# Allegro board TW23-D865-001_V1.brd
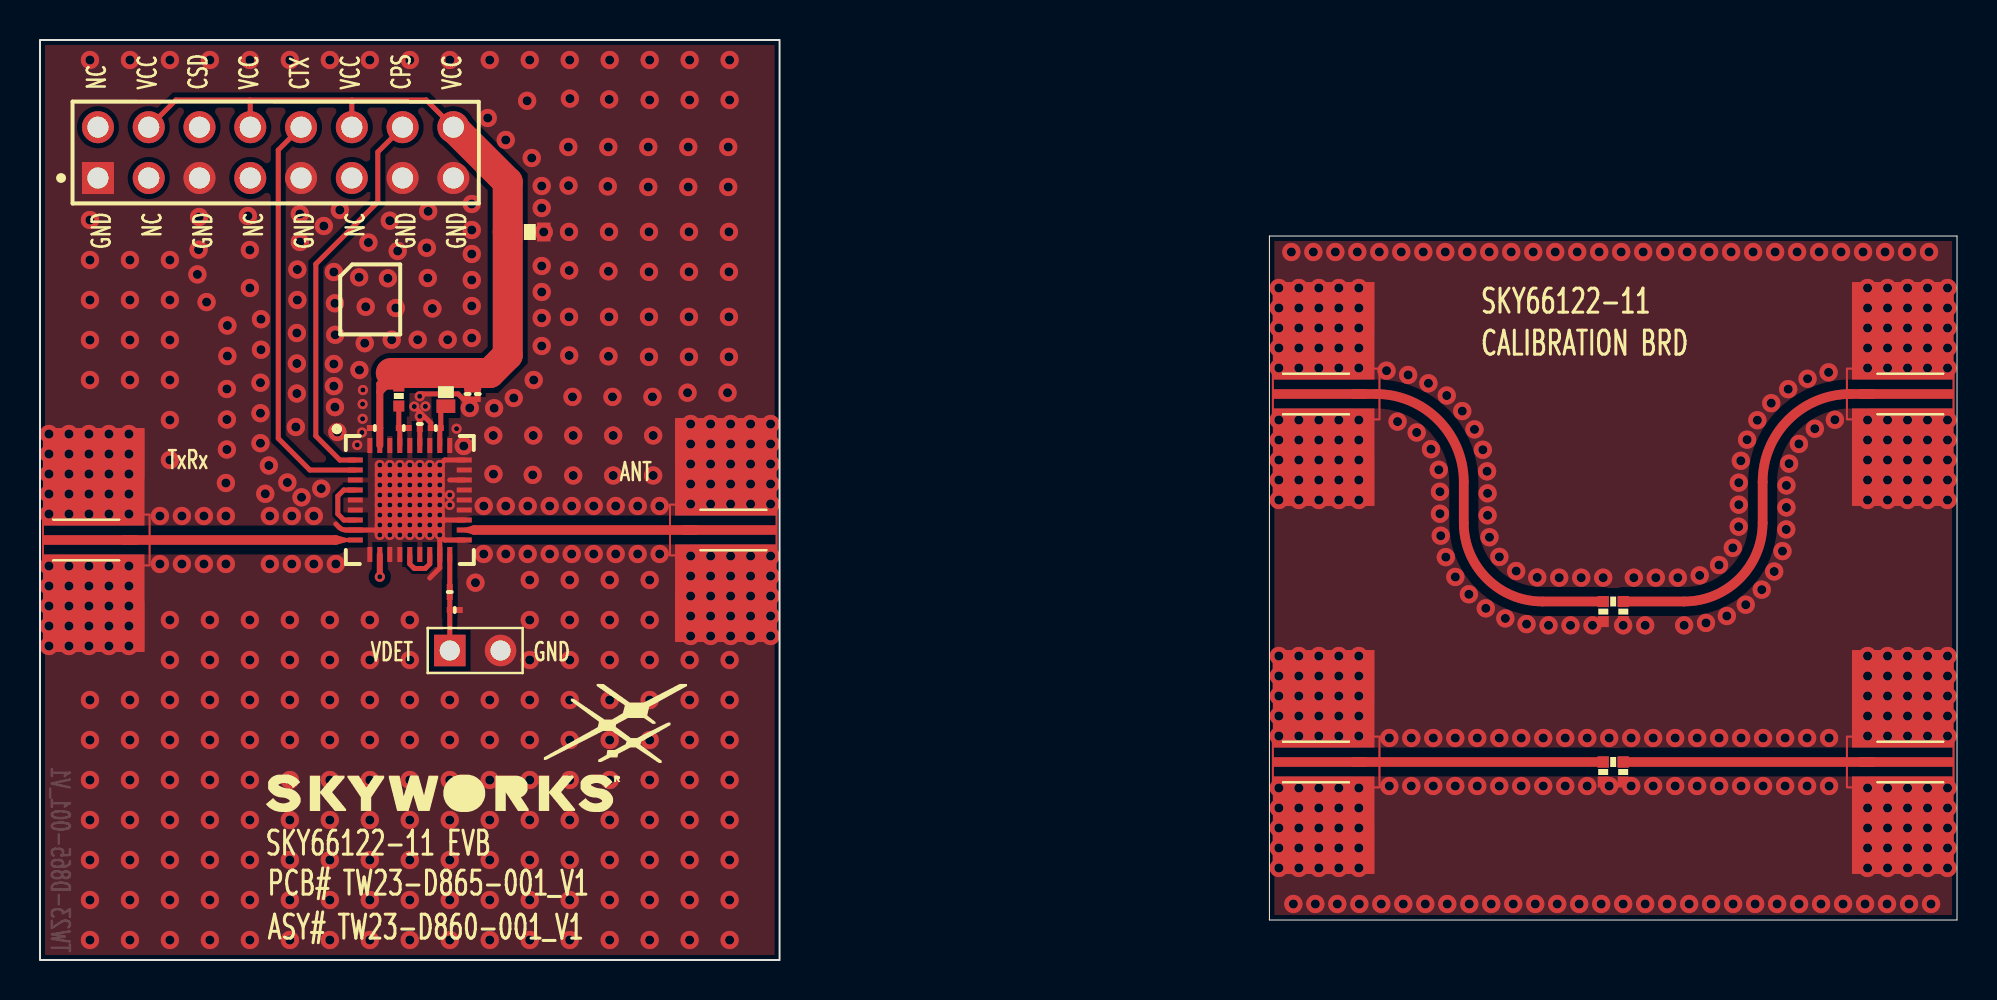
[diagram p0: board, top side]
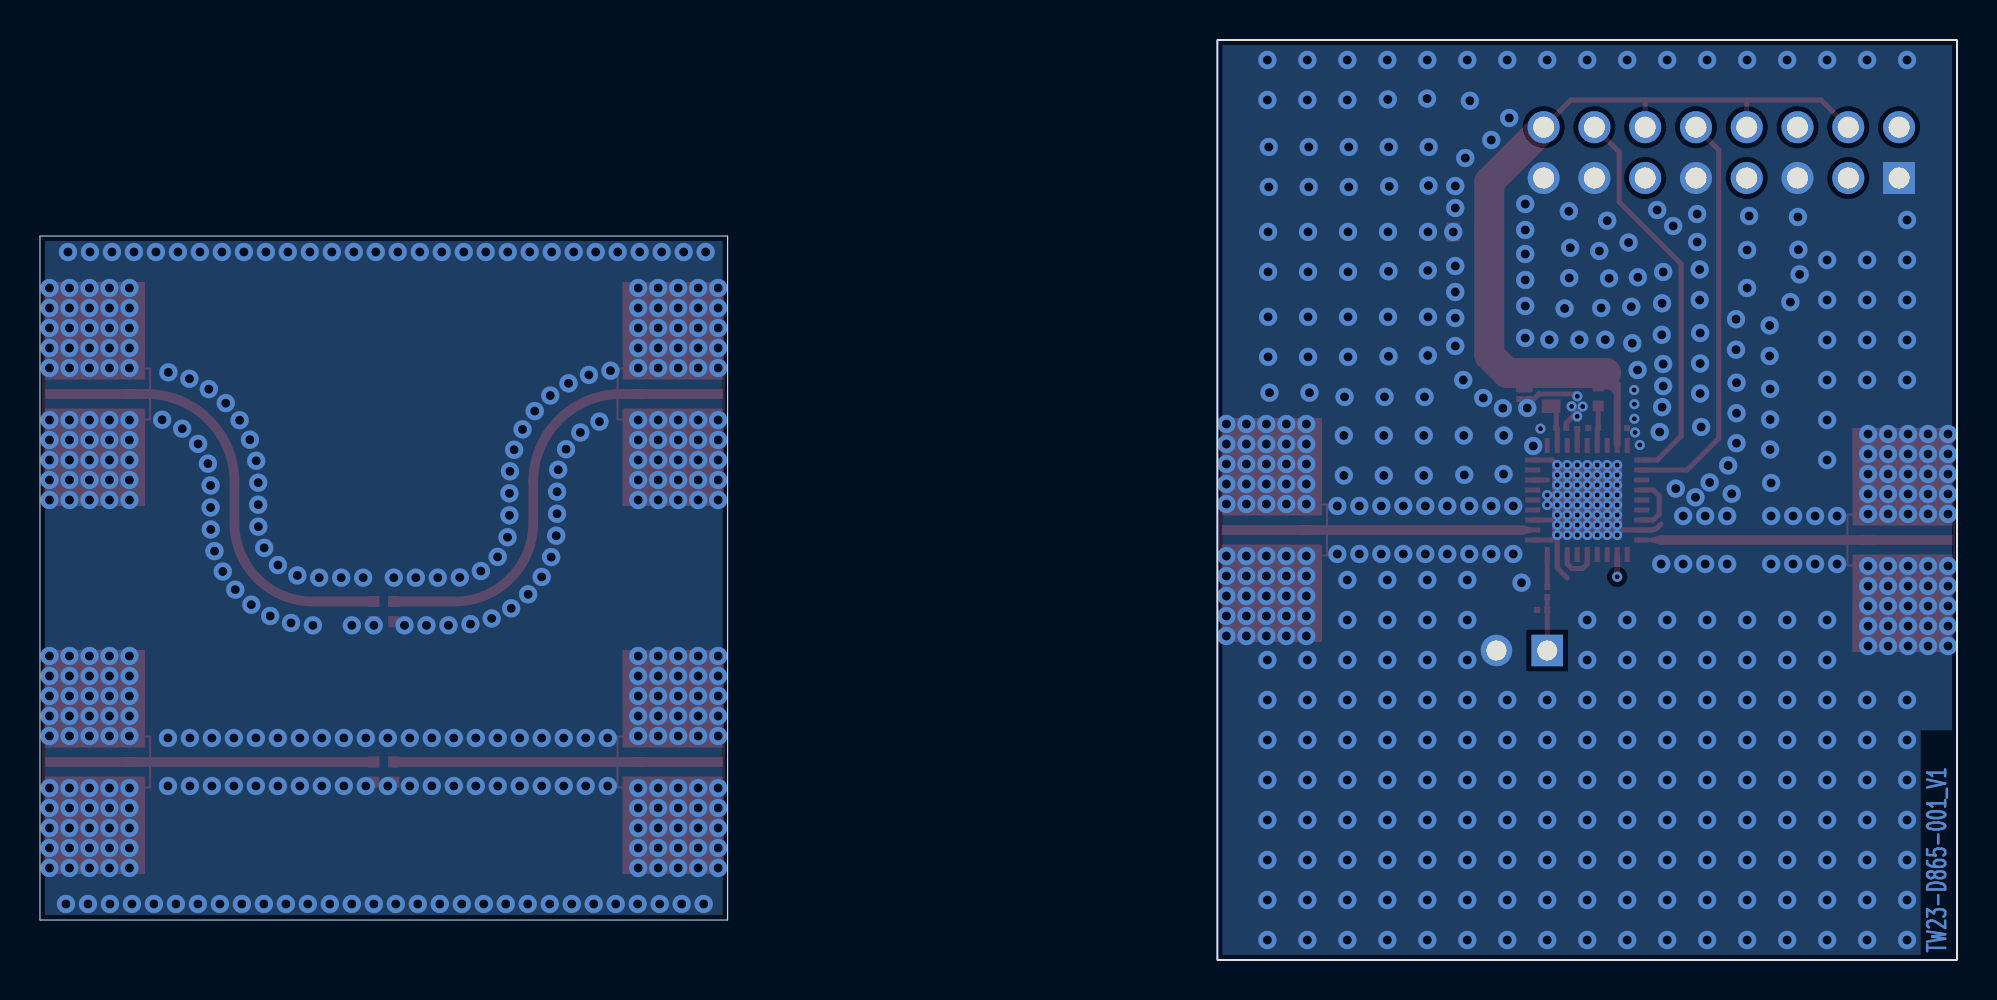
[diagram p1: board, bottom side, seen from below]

Outline 95.9 x 46 mm; copper layers: TOP, L2, L3, BOTTOM. Coordinates in mm from the lower left corner of the outline.
Outline path: rectangle 0,0 37,46 ; 61.5,36.2 61.5,2 95.9,2 95.9,36.2 61.5,36.2

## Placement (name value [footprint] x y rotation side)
ANT  SMA  [SSMA]  95.72 9.9 0 top
C1  -  [0201]  19.8 26.6 0 top
C3  -  [0201]  16.75 26.6 0 top
C5  -  [0201]  18.2 26.6 180 top
C6  -  [0201]  21.39 28.3 270 top
C7  -  [0201]  21.9 28.3 270 top
C8  -  [0201]  19 26.8 270 top
C9  -  [0603]  24.5 36.4 0 top
C10  -  [0201]  20.75 17.5 0 top
J1  ANT  [SSMA]  36.85 21.5 0 top
J2  Header_7  [HDR2540P1RST-2]  21.77 15.47 0 top
J3  TX_RX  [SSMA]  0.15 21 180 top
J5  CON16A  [HDRV2X8_2540P]  2.9 39.1 0 top
J44  SMA  [SSMA]  95.72 28.3 0 top
JM44  SMA  [SSMA]  61.68 28.3 180 top
L3  -  [0402]  17.95 28.2 90 top
L4  -  [0603]  20.3 28.39 90 top
NOREF  -  []  -46.4 -55.15 0 top
NOREF#2  -  []  95.9 2 90 top
NOREF#3  -  []  61.5 36.2 0 top
NOREF#4  -  []  120.8 27.75 0 top
NOREF#5  -  []  11.3 7.4 0 top
NOREF#6  -  []  0 0 90 top
NOREF#7  -  []  0 46 0 top
NOREF#8  -  []  -46.45 -113.82 0 top
NOREF#9  -  []  118.6 -25.15 0 top
NOREF#10  -  []  151.3 -8.35 0 top
R1  -  [0201]  20.5 18.4 270 top
R2  0201  [0402]  78.7 9.9 0 top
R3  0201  [0402]  78.2 9.4 90 top
R4  0201  [0402]  79.2 9.4 90 top
R5  0201  [0402]  78.7 17.93 0 top
R6  0201  [0402]  78.2 17.42 90 top
R7  0201  [0402]  79.2 17.42 90 top
TX_RX  SMA  [SSMA]  61.68 9.9 180 top
U1  SKY66122-11  [MCM50P600X600-36-302]  18.5 23 0 top

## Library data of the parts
ANT J1 J3 J44 JM44 TX_RX = SMA_3pin: User Part Number: SMA_S
C1 C3 C5 C8 = C
C6 C7 C10 = CAP NP: User Part Number: 5406R29-036
C9 = CAP NP
J2 = Header_7
J5 = CON16A_0
L3 L4 = INDUCTOR/SM
R1 = RES_FIXED: User Part Number: 5424R27-134
R2-R7 = RES_FIXED
U1 = GS6_LowBand_MCM_6

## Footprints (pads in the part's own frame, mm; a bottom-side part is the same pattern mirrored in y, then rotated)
0201
  rect 0.3x0.3 smd: 1(-0.25,0) 2(0.25,0)
0402
  rect 0.55x0.55 smd: 1(-0.5,0) 2(0.5,0)
0603
  rect 0.68x0.94 smd: 1(-0.7,0) 2(0.7,0)
HDR2540P1RST-2
  rect 1.575x1.575 hole 1: 1(-1.27,0)
  round 1.575 hole 1: 2(1.27,0)
HDRV2X8_2540P
  rect 1.6x1.6 hole 1.05: 1(0,0)
  round 1.6 hole 1.05: 2(0,2.54) 3(2.54,0) 4(2.54,2.54) 5(5.08,0) 6(5.08,2.54) 7(7.62,0) 8(7.62,2.54) 9(10.16,0) 10(10.16,2.54) 11(12.7,0) 12(12.7,2.54) 13(15.24,0) 14(15.24,2.54) 15(17.78,0) 16(17.78,2.54)
MCM50P600X600-36-302
  rect 0.75x0.25 smd: 1(-2.725,2) 2(-2.725,1.5) 3(-2.725,1) 4(-2.725,0.5) 5(-2.725,0) 6(-2.725,-0.5) 7(-2.725,-1) 8(-2.725,-1.5) 9(-2.725,-2) 19(2.725,-2) 20(2.725,-1.5) 21(2.725,-1) 22(2.725,-0.5) 23(2.725,0) 24(2.725,0.5) 25(2.725,1) 26(2.725,1.5) 27(2.725,2)
  rect 0.25x0.75 smd: 10(-2,-2.725) 11(-1.5,-2.725) 12(-1,-2.725) 13(-0.5,-2.725) 14(0,-2.725) 15(0.5,-2.725) 16(1,-2.725) 17(1.5,-2.725) 18(2,-2.725) 28(2,2.725) 29(1.5,2.725) 30(1,2.725) 31(0.5,2.725) 32(0,2.725) 33(-0.5,2.725) 34(-1,2.725) 35(-1.5,2.725) 36(-2,2.725)
  rect 3.5x3.5 smd: 37(0,0)
SSMA
  rect 0.762x0.483 smd: 1(-4.341,0)
  rect 5.075x2.54 smd: 2(-2.535,4.318) 3(-2.535,-4.318)

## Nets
GND: C1.1 C3.1 C5.1 C6.2 C7.2 C8.1 C9.2 C10.2 J1.2(GND_SIGNAL#2) J1.3(GND_SIGNAL#3) J2.2 J3.2(GND_SIGNAL#2) J3.3(GND_SIGNAL#3) J5.1(GND#1) J5.5(GND#5) J5.9(GND#9) J5.13(GND#13) J5.15 U1.3(P03_GND) U1.5(P05_GND) U1.6(P06_GND) U1.8(P08_GND) U1.10(P10_GND) U1.12(P12_GND) U1.13(P13_GND) U1.15(P15_GND) U1.17(P17_GNF) U1.19(P19_GND) U1.21(P21_GND) U1.22(P22_GND) U1.23(P23_GND) U1.24(P24_GND) U1.25(P25_GND) U1.26(P26_GND) U1.27(P27_GND) U1.28(P28_GND) U1.30(P30_GND) U1.32(P32_GND) U1.34(P34_GND) U1.36(P36_GND) U1.37(GND0)
GND_FIELD SIGNAL: ANT.2(GND_SIGNAL#2) ANT.3(GND_SIGNAL#3) J44.2(GND_SIGNAL#2) J44.3(GND_SIGNAL#3) JM44.2(GND_SIGNAL#2) JM44.3(GND_SIGNAL#3) R3.1 R4.1 R6.1 R7.1 TX_RX.2(GND_SIGNAL#2) TX_RX.3(GND_SIGNAL#3)
VCC: C3.2 C6.1 C7.1 C9.1 J5.4(VCC#4) J5.8(VCC#8) J5.12(VCC#12) J5.16(VCC#16) L3.2 L4.2 U1.35(P35_VSUP1)
CPS: J5.14(CPS) U1.1(P01_CPS)
CSD: J5.6(CSD) U1.11(P11_CSD)
CTX: J5.10(CTX) U1.2(P02_CTX)
N16669932: J3.1(SIG) U1.9(P09_TXRX)
N16681438: U1.4(P04_PA_IN) U1.7(P07_TX_FLT)
N16682076: U1.14(P14_LNA_IN) U1.16(P16_RX_FLT)
N16682361: R1.1 U1.18(P18_VDET)
N16682536: C10.1 J2.1 R1.2
N16682817: J1.1(SIG) U1.20(P20_ANT)
N16684168: C1.2 L4.1 U1.29(29_VCC2)
N16686225: C5.2 L3.1 U1.33(P33_VCC1)
N16698570: JM44.1(SIG) R5.1 R6.2
N16698590: J44.1(SIG) R5.2 R7.2
N16698666: R2.1 R3.2 TX_RX.1(SIG)
N16698686: ANT.1(SIG) R2.2 R4.2
N1664008529: C8.2 U1.31(P31_VCC0)

Pads without a net: J5 2 3 7 11

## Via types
v1: diameter 0.915, hole 0.455, TOP to BOTTOM, 808 vias
v2: diameter 0.508, hole 0.254, TOP to BOTTOM, 69 vias

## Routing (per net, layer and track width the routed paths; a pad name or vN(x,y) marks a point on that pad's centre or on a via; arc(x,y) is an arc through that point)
GND: length 13.7
  TOP w0.2: v2(18.99,28.18) 19.01,28.2
  TOP w0.25: 19.01,28.2 19.12,28.31 20.91,28.31 21.2,28.02 21.22,28.05 C6.2 C7.2 ; v2(20,21.75) 20.25,22 U1.21 ; 14.8,21.8 14.96,21.64 arc(15.11,21.54) 15.29,21.5 U1.8 16.75,21.5 v2(17,21.25) ; C1.1 19.55,26.85 18.9,27.5 ; U1.25 20.5,24 ; U1.27 20.25,25 v2(20,24.75) ; 19.5,19.1 20,19.6 U1.17 v2(20,21.25) 20.25,21 U1.19
  vias: v1(0.45,26.3) v1(0.45,25.3) v1(0.45,24.3) v1(0.45,23.3) v1(0.45,22.3) v1(0.45,19.7) v1(0.45,18.7) v1(0.45,17.7) v1(0.45,16.7) v1(0.45,15.7) v1(1.45,26.3) v1(1.45,25.3) v1(1.45,24.3) v1(1.45,23.3) v1(1.45,22.3) v1(1.45,19.7) v1(1.45,18.7) v1(1.45,17.7) v1(1.45,16.7) v1(1.45,15.7) v1(2.45,26.3) v1(2.45,25.3) v1(2.45,24.3) v1(2.45,23.3) v1(2.45,22.3) v1(2.45,19.7) v1(2.45,18.7) v1(2.45,17.7) v1(2.45,16.7) v1(2.45,15.7) v1(2.5,45) v1(2.5,37) v1(2.5,35) v1(2.5,33) v1(2.5,31) v1(2.5,29) v1(2.5,13) v1(2.5,11) v1(2.5,9) v1(2.5,7) v1(2.5,5) v1(2.5,3) v1(2.5,1) v1(3.45,26.3) v1(3.45,25.3) v1(3.45,24.3) v1(3.45,23.3) v1(3.45,22.3) v1(3.45,19.7) v1(3.45,18.7) v1(3.45,17.7) v1(3.45,16.7) v1(3.45,15.7) v1(4.5,45) v1(4.5,35) v1(4.5,33) v1(4.5,31) v1(4.5,29) v1(4.45,26.3) v1(4.45,25.3) v1(4.45,24.3) v1(4.45,23.3) v1(4.45,22.3) v1(4.45,19.7) v1(4.45,18.7) v1(4.45,17.7) v1(4.45,16.7) v1(4.45,15.7) v1(4.5,13) v1(4.5,11) v1(4.5,9) v1(4.5,7) v1(4.5,5) v1(4.5,3) v1(4.5,1) v1(6,22.2) v1(6,19.8) v1(6.5,45) v1(6.5,35) v1(6.5,33) v1(6.5,31) v1(6.5,29) v1(6.5,27) v1(6.5,25) v1(6.5,17) v1(6.5,15) v1(6.5,13) v1(6.5,11) v1(6.5,9) v1(6.5,7) v1(6.5,5) v1(6.5,3) v1(6.5,1) v1(7.1,22.2) v1(7.1,19.8) v1(7.93,35.52) v1(7.88,34.28) v1(7.96,37.15) v1(8.2,22.2) v1(8.2,19.8) v1(8.33,32.9) v1(8.5,45) v1(8.5,17) v1(8.5,15) v1(8.5,13) v1(8.5,11) v1(8.5,9) v1(8.5,7) v1(8.5,5) v1(8.5,3) v1(8.5,1) v1(9.3,23.85) v1(9.3,22.2) v1(9.3,19.8) v1(9.38,31.72) v1(9.38,30.2) v1(9.35,28.55) v1(9.35,27.02) v1(9.35,25.52) v1(10.4,37.2) v1(10.5,45) v1(10.5,35.5) v1(10.5,33.6) v1(10.5,17) v1(10.5,15) v1(10.5,13) v1(10.5,11) v1(10.5,9) v1(10.5,7) v1(10.5,5) v1(10.5,3) v1(10.5,1) v1(11.03,28.86) v1(11.03,27.34) v1(11.03,25.84) v1(11.05,32.04) v1(11.05,30.52) v1(11.27,23.31) v1(11.45,24.72) v1(11.5,22.2) v1(11.5,19.8) v1(12.38,23.88) v1(12.5,45) v1(12.5,17) v1(12.5,15) v1(12.5,13) v1(12.5,11) v1(12.5,9) v1(12.5,7) v1(12.5,5) v1(12.5,3) v1(12.5,1) v1(12.6,22.2) v1(12.6,19.8) v1(12.85,31.35) v1(12.85,29.82) v1(12.85,28.32) v1(12.8,26.65) v1(12.88,34.53) v1(12.88,33) v1(13,37.3) v1(13,35.9) v1(13.09,23.13) v1(13.7,22.2) v1(13.7,19.8) v1(14.07,23.57) v1(14.2,36.7) v1(14.5,45) v1(14.5,17) v1(14.5,15) v1(14.5,13) v1(14.5,11) v1(14.5,9) v1(14.5,7) v1(14.5,5) v1(14.5,3) v1(14.5,1) v1(14.7,34.4) v1(14.7,29.8) v1(14.7,28.7) v1(14.75,32.84) v1(14.77,31.26) v1(14.75,27.64) v1(14.8,19.8) v1(14.88,26.4) v1(15,37.5) v1(15.96,34.14) v1(15.98,29.5) v1(16.24,30.84) v1(16.3,32.66) v1(16.43,35.88) v1(16.5,45) v1(16.5,17) v1(16.5,15) v1(16.5,13) v1(16.5,11) v1(16.5,9) v1(16.5,7) v1(16.5,5) v1(16.5,3) v1(16.5,1) v1(17.41,34.09) v1(17.5,36.97) v1(17.59,31.02) v1(17.8,32.6) v1(17.89,35.45) v1(18.5,45) v1(18.5,17) v1(18.5,15) v1(18.5,13) v1(18.5,11) v1(18.5,9) v1(18.5,7) v1(18.5,5) v1(18.5,3) v1(18.5,1) v1(18.89,31.02) v1(19.42,37.44) v1(19.35,35.61) v1(19.4,34.1) v1(19.63,32.58) v1(20.39,31.02) v1(20.5,45) v1(20.5,13) v1(20.5,11) v1(20.5,9) v1(20.5,7) v1(20.5,5) v1(20.5,3) v1(20.5,1) v1(21.2,25.7) v1(21.5,27.6) v1(21.6,37.8) v1(21.6,36.5) v1(21.6,35.3) v1(21.6,34) v1(21.6,32.7) v1(21.6,31.1) v1(21.79,18.86) v1(22.2,22.7) v1(22.2,20.3) v1(22.4,42.1) v1(22.5,45) v1(22.5,13) v1(22.5,11) v1(22.5,9) v1(22.5,7) v1(22.5,5) v1(22.5,3) v1(22.5,1) v1(22.72,27.59) v1(22.67,26.22) v1(22.69,24.29) v1(23.3,41) v1(23.3,22.7) v1(23.3,20.3) v1(23.7,28.1) v1(24.37,42.96) v1(24.4,22.7) v1(24.4,20.3) v1(24.5,45) v1(24.5,19) v1(24.5,17) v1(24.5,15) v1(24.5,13) v1(24.5,11) v1(24.5,9) v1(24.5,7) v1(24.5,5) v1(24.5,3) v1(24.5,1) v1(24.6,40.1) v1(24.7,29) v1(24.67,26.22) v1(24.65,24.25) v1(25.1,38.7) v1(25.1,37.6) v1(25.1,34.7) v1(25.1,33.4) v1(25.1,32.1) v1(25.1,30.7) v1(25.2,36.4) v1(25.5,22.7) v1(25.5,20.3) v1(26.43,40.65) v1(26.44,38.72) v1(26.5,45) v1(26.51,43.07) v1(26.46,36.41) v1(26.48,34.48) v1(26.46,32.16) v1(26.48,30.22) v1(26.5,19) v1(26.5,17) v1(26.5,15) v1(26.5,13) v1(26.5,11) v1(26.5,9) v1(26.5,7) v1(26.5,5) v1(26.5,3) v1(26.5,1) v1(26.64,28.15) v1(26.6,22.7) v1(26.6,20.3) v1(26.67,26.22) v1(26.67,24.22) v1(27.7,22.7) v1(27.7,20.3) v1(28.43,40.65) v1(28.41,38.68) v1(28.44,34.44) v1(28.44,30.18) v1(28.5,45) v1(28.48,43.03) v1(28.46,36.41) v1(28.46,32.16) v1(28.5,19) v1(28.5,17) v1(28.5,15) v1(28.5,13) v1(28.5,11) v1(28.5,9) v1(28.5,7) v1(28.5,5) v1(28.5,3) v1(28.5,1) v1(28.64,28.15) v1(28.67,26.22) v1(28.67,24.22) v1(28.8,22.7) v1(28.8,20.3) v1(29.9,22.7) v1(29.9,20.3) v1(30.43,40.65) v1(30.43,38.65) v1(30.5,45) v1(30.5,43) v1(30.46,36.41) v1(30.46,34.41) v1(30.46,32.16) v1(30.46,30.15) v1(30.5,19) v1(30.5,17) v1(30.5,15) v1(30.5,13) v1(30.5,11) v1(30.5,9) v1(30.5,7) v1(30.5,5) v1(30.5,3) v1(30.5,1) v1(30.64,28.15) v1(30.67,26.22) v1(30.67,24.22) v1(31,22.7) v1(31,20.3) v1(32.43,40.65) v1(32.43,38.65) v1(32.4,28.36) v1(32.5,45) v1(32.5,43) v1(32.46,36.41) v1(32.46,34.41) v1(32.46,32.16) v1(32.46,30.15) v1(32.55,26.8) v1(32.55,25.8) v1(32.55,24.8) v1(32.55,23.8) v1(32.55,22.8) v1(32.55,20.2) v1(32.55,19.2) v1(32.55,18.2) v1(32.55,17.2) v1(32.55,16.2) v1(32.5,15) v1(32.5,13) v1(32.5,11) v1(32.5,9) v1(32.5,7) v1(32.5,5) v1(32.5,3) v1(32.5,1) v1(33.55,26.8) v1(33.55,25.8) v1(33.55,24.8) v1(33.55,23.8) v1(33.55,22.8) v1(33.55,20.2) v1(33.55,19.2) v1(33.55,18.2) v1(33.55,17.2) v1(33.55,16.2) v1(34.43,40.65) v1(34.43,38.65) v1(34.4,28.36) v1(34.5,45) v1(34.5,43) v1(34.46,36.41) v1(34.46,34.41) v1(34.46,32.16) v1(34.46,30.15) v1(34.55,26.8) v1(34.55,25.8) v1(34.55,24.8) v1(34.55,23.8) v1(34.55,22.8) v1(34.55,20.2) v1(34.55,19.2) v1(34.55,18.2) v1(34.55,17.2) v1(34.55,16.2) v1(34.5,15) v1(34.5,13) v1(34.5,11) v1(34.5,9) v1(34.5,7) v1(34.5,5) v1(34.5,3) v1(34.5,1) v1(35.55,26.8) v1(35.55,25.8) v1(35.55,24.8) v1(35.55,23.8) v1(35.55,22.8) v1(35.55,20.2) v1(35.55,19.2) v1(35.55,18.2) v1(35.55,17.2) v1(35.55,16.2) v1(36.55,26.8) v1(36.55,25.8) v1(36.55,24.8) v1(36.55,23.8) v1(36.55,22.8) v1(36.55,20.2) v1(36.55,19.2) v1(36.55,18.2) v1(36.55,17.2) v1(36.55,16.2) v2(15.87,25.75) v2(16.14,27.79) v2(16.14,27.06) v2(16.11,26.38) v2(16.16,28.5) v2(17,24.75) v2(17,24.25) v2(17,23.75) v2(17,23.25) v2(17,22.75) v2(17,22.25) v2(17,21.75) v2(17.5,24.75) v2(17.5,24.25) v2(17.5,23.75) v2(17.5,23.25) v2(17.5,22.75) v2(17.5,22.25) v2(17.5,21.75) v2(17.5,21.25) v2(18,24.75) v2(18,24.25) v2(18,23.75) v2(18,23.25) v2(18,22.75) v2(18,22.25) v2(18,21.75) v2(18,21.25) v2(18.5,24.75) v2(18.5,24.25) v2(18.5,23.75) v2(18.5,23.25) v2(18.5,22.75) v2(18.5,22.25) v2(18.5,21.75) v2(18.5,21.25) v2(18.73,27.68) v2(19,27.18) v2(19,24.75) v2(19,24.25) v2(19,23.75) v2(19,23.25) v2(19,22.75) v2(19,22.25) v2(19,21.75) v2(19,21.25) v2(19.28,27.68) v2(19.5,24.75) v2(19.5,24.25) v2(19.5,23.75) v2(19.5,23.25) v2(19.5,22.75) v2(19.5,22.25) v2(19.5,21.75) v2(19.5,21.25) v2(20,24.25) v2(20,23.75) v2(20,23.25) v2(20,22.75) v2(20,22.25) v2(20.5,23.25) v2(20.5,22.75) v2(20.84,26.56)
GND_FIELD SIGNAL:
  vias: v1(61.98,33.6) v1(61.98,32.6) v1(61.98,31.6) v1(61.98,30.6) v1(61.98,29.6) v1(61.98,27) v1(61.98,26) v1(61.98,25) v1(61.98,24) v1(61.98,23) v1(61.98,15.2) v1(61.98,14.2) v1(61.98,13.2) v1(61.98,12.2) v1(61.98,11.2) v1(61.98,8.6) v1(61.98,7.6) v1(61.98,6.6) v1(61.98,5.6) v1(61.98,4.6) v1(62.6,35.4) v1(62.7,2.8) v1(62.98,33.6) v1(62.98,32.6) v1(62.98,31.6) v1(62.98,30.6) v1(62.98,29.6) v1(62.98,27) v1(62.98,26) v1(62.98,25) v1(62.98,24) v1(62.98,23) v1(62.98,15.2) v1(62.98,14.2) v1(62.98,13.2) v1(62.98,12.2) v1(62.98,11.2) v1(62.98,8.6) v1(62.98,7.6) v1(62.98,6.6) v1(62.98,5.6) v1(62.98,4.6) v1(63.7,35.4) v1(63.8,2.8) v1(63.98,33.6) v1(63.98,32.6) v1(63.98,31.6) v1(63.98,30.6) v1(63.98,29.6) v1(63.98,27) v1(63.98,26) v1(63.98,25) v1(63.98,24) v1(63.98,23) v1(63.98,15.2) v1(63.98,14.2) v1(63.98,13.2) v1(63.98,12.2) v1(63.98,11.2) v1(63.98,8.6) v1(63.98,7.6) v1(63.98,6.6) v1(63.98,5.6) v1(63.98,4.6) v1(64.8,35.4) v1(64.9,2.8) v1(64.97,33.6) v1(64.97,32.6) v1(64.97,31.6) v1(64.97,30.6) v1(64.97,29.6) v1(64.97,27) v1(64.97,26) v1(64.97,25) v1(64.97,24) v1(64.97,23) v1(64.97,15.2) v1(64.97,14.2) v1(64.97,13.2) v1(64.97,12.2) v1(64.97,11.2) v1(64.97,8.6) v1(64.97,7.6) v1(64.97,6.6) v1(64.97,5.6) v1(64.97,4.6) v1(65.9,35.4) v1(65.97,33.6) v1(65.97,32.6) v1(65.97,31.6) v1(65.97,30.6) v1(65.97,29.6) v1(65.97,27) v1(65.97,26) v1(65.97,25) v1(65.97,24) v1(65.97,23) v1(65.97,15.2) v1(65.97,14.2) v1(65.97,13.2) v1(65.97,12.2) v1(65.97,11.2) v1(65.97,8.6) v1(65.97,7.6) v1(65.97,6.6) v1(65.97,5.6) v1(65.97,4.6) v1(66,2.8) v1(67,35.4) v1(67.1,2.8) v1(67.36,29.47) v1(67.5,11.1) v1(67.5,8.7) v1(67.91,26.92) v1(68.1,35.4) v1(68.2,2.8) v1(68.44,29.25) v1(68.6,11.1) v1(68.6,8.7) v1(68.87,26.38) v1(69.2,35.4) v1(69.3,2.8) v1(69.46,28.83) v1(69.58,25.54) v1(69.7,11.1) v1(69.7,8.7) v1(69.98,24.51) v1(70.03,23.41) v1(70.03,22.31) v1(70.07,21.21) v1(70.3,35.4) v1(70.33,20.14) v1(70.37,28.22) v1(70.4,2.8) v1(70.8,19.15) v1(70.8,11.1) v1(70.8,8.7) v1(71.15,27.45) v1(71.4,35.4) v1(71.48,18.29) v1(71.5,2.8) v1(71.76,26.53) v1(71.9,11.1) v1(71.9,8.7) v1(72.18,25.51) v1(72.33,17.58) v1(72.39,24.43) v1(72.42,23.33) v1(72.42,22.23) v1(72.5,35.4) v1(72.51,21.14) v1(72.6,2.8) v1(73.01,20.16) v1(73,11.1) v1(73,8.7) v1(73.3,17.08) v1(73.6,35.4) v1(73.7,2.8) v1(73.85,19.45) v1(74.1,11.1) v1(74.1,8.7) v1(74.37,16.79) v1(74.7,35.4) v1(74.8,2.8) v1(74.9,19.13) v1(75.2,11.1) v1(75.2,8.7) v1(75.47,16.73) v1(75.8,35.4) v1(75.9,2.8) v1(76,19.12) v1(76.3,11.1) v1(76.3,8.7) v1(76.57,16.73) v1(76.9,35.4) v1(77,2.8) v1(77.1,19.12) v1(77.4,11.1) v1(77.4,8.7) v1(77.67,16.73) v1(78,35.4) v1(78.1,2.8) v1(78.2,19.12) v1(78.5,11.1) v1(78.5,8.7) v1(79.1,35.4) v1(79.2,16.73) v1(79.2,2.8) v1(79.6,11.1) v1(79.6,8.7) v1(79.73,19.12) v1(80.2,35.4) v1(80.3,16.73) v1(80.3,2.8) v1(80.7,11.1) v1(80.7,8.7) v1(80.83,19.12) v1(81.3,35.4) v1(81.4,2.8) v1(81.8,11.1) v1(81.8,8.7) v1(81.93,19.12) v1(82.25,16.73) v1(82.4,35.4) v1(82.5,2.8) v1(82.9,11.1) v1(82.9,8.7) v1(83.03,19.23) v1(83.34,16.85) v1(83.5,35.4) v1(83.6,2.8) v1(84,19.75) v1(84,11.1) v1(84,8.7) v1(84.39,17.2) v1(84.6,35.4) v1(84.68,20.61) v1(84.7,2.8) v1(84.98,23.87) v1(84.98,22.77) v1(84.98,21.67) v1(85.08,24.96) v1(85.1,11.1) v1(85.1,8.7) v1(85.33,17.76) v1(85.4,26.02) v1(85.7,35.4) v1(85.8,2.8) v1(85.91,26.99) v1(86.13,18.52) v1(86.2,11.1) v1(86.2,8.7) v1(86.61,27.84) v1(86.8,35.4) v1(86.75,19.42) v1(86.9,2.8) v1(87.17,20.44) v1(87.3,11.1) v1(87.3,8.7) v1(87.37,23.73) v1(87.37,22.63) v1(87.36,21.53) v1(87.45,28.54) v1(87.5,24.82) v1(87.9,35.4) v1(87.99,25.8) v1(88,2.8) v1(88.42,29.06) v1(88.4,11.1) v1(88.4,8.7) v1(88.78,26.56) v1(89,35.4) v1(89.1,2.8) v1(89.48,29.38) v1(89.5,11.1) v1(89.5,8.7) v1(89.79,27.01) v1(90.1,35.4) v1(90.2,2.8) v1(91.2,35.4) v1(91.3,2.8) v1(91.42,33.6) v1(91.42,32.6) v1(91.42,31.6) v1(91.42,30.6) v1(91.42,29.6) v1(91.42,27) v1(91.42,26) v1(91.42,25) v1(91.42,24) v1(91.42,23) v1(91.42,15.2) v1(91.42,14.2) v1(91.42,13.2) v1(91.42,12.2) v1(91.42,11.2) v1(91.42,8.6) v1(91.42,7.6) v1(91.42,6.6) v1(91.42,5.6) v1(91.42,4.6) v1(92.3,35.4) v1(92.42,33.6) v1(92.42,32.6) v1(92.42,31.6) v1(92.42,30.6) v1(92.42,29.6) v1(92.42,27) v1(92.42,26) v1(92.42,25) v1(92.42,24) v1(92.42,23) v1(92.42,15.2) v1(92.42,14.2) v1(92.42,13.2) v1(92.42,12.2) v1(92.42,11.2) v1(92.42,8.6) v1(92.42,7.6) v1(92.42,6.6) v1(92.42,5.6) v1(92.42,4.6) v1(92.4,2.8) v1(93.4,35.4) v1(93.42,33.6) v1(93.42,32.6) v1(93.42,31.6) v1(93.42,30.6) v1(93.42,29.6) v1(93.42,27) v1(93.42,26) v1(93.42,25) v1(93.42,24) v1(93.42,23) v1(93.42,15.2) v1(93.42,14.2) v1(93.42,13.2) v1(93.42,12.2) v1(93.42,11.2) v1(93.42,8.6) v1(93.42,7.6) v1(93.42,6.6) v1(93.42,5.6) v1(93.42,4.6) v1(93.5,2.8) v1(94.42,33.6) v1(94.42,32.6) v1(94.42,31.6) v1(94.42,30.6) v1(94.42,29.6) v1(94.42,27) v1(94.42,26) v1(94.42,25) v1(94.42,24) v1(94.42,23) v1(94.42,15.2) v1(94.42,14.2) v1(94.42,13.2) v1(94.42,12.2) v1(94.42,11.2) v1(94.42,8.6) v1(94.42,7.6) v1(94.42,6.6) v1(94.42,5.6) v1(94.42,4.6) v1(94.5,35.4) v1(94.6,2.8) v1(95.42,33.6) v1(95.42,32.6) v1(95.42,31.6) v1(95.42,30.6) v1(95.42,29.6) v1(95.42,27) v1(95.42,26) v1(95.42,25) v1(95.42,24) v1(95.42,23) v1(95.42,15.2) v1(95.42,14.2) v1(95.42,13.2) v1(95.42,12.2) v1(95.42,11.2) v1(95.42,8.6) v1(95.42,7.6) v1(95.42,6.6) v1(95.42,5.6) v1(95.42,4.6)
VCC: length 47.8
  TOP w0.25: 10.5,43 6.8,43 J5.4 ; 10.5,43 10.52,42.98 J5.8 ; 10.5,43 15.6,43 ; 15.6,43 19.32,43 J5.16 ; 15.6,43 J5.12 ; L4.2 20.3,29.07 20.38,29 ; C6.1 21.39,29 20.75,29
  TOP w0.35: 17,25.72 C3.2 17,28.4 ; 17,28.4 17,28.8 17.55,29.35 ; 17,28.4 17.3,28.7 L3.2 18.25,29 20.75,29 ; C9.1 23.4,36.4 ; C7.1 C6.1
  TOP w1.5: 17.55,29.35 22.5,29.35 23.4,30.25 23.4,38.9 20.68,41.62 J5.16
CPS: length 19.7
  TOP w0.25: J5.14 16.9,40.4 16.9,37.9 13.8,34.8 13.8,26.2 15,25 U1.1
CSD: length 32.3
  TOP w0.3: U1.11 v2(17,19.16)
  L3 w0.25: J5.6 9.1,40.52 9.1,33.6 10.23,32.47 10.23,19.16 11.4,18 15.84,18 v2(17,19.16)
CTX: length 20.5
  TOP w0.25: J5.10 11.92,40.5 11.92,26.08 13.5,24.5 U1.2
N16669932: length 11.3
  TOP w0.2: 14.78,21 U1.9
  TOP w0.483: J3.1 14.78,21
N16681438: length 2.9
  TOP w0.25: U1.4 15.2,23.5 14.9,23.2 14.9,22.3 15.2,22 U1.7
N16682076: length 2.1
  TOP w0.25: U1.14 18.5,19.8 18.7,19.6 18.72,19.6 18.74,19.57 19.26,19.57 19.28,19.6 19.3,19.6 19.5,19.8 U1.16
N16682361: length 1.6
  TOP w0.25: U1.18 R1.1
N16682536: length 2.7
  TOP w0.25: J2.1 C10.1 R1.2
N16682817: length 11.3
  TOP w0.2: 21.72,21.5 U1.20
  TOP w0.483: J1.1 21.72,21.5
N16684168: length 2.1
  TOP w0.25: L4.1 20.05,27.43 C1.2 20,26.55 20,25.72
N16686225: length 2
  TOP w0.25: 18,25.72 18,26.55 C5.2 L3.1
N16698570: length 19
  TOP w0.483: R5.1 75.15,17.93 arc(72.38,19.08) 71.22,21.85 71.22,23.9 arc(69.94,27.01) 66.83,28.3 JM44.1
N16698590: length 19
  TOP w0.483: J44.1 90.57,28.3 arc(87.46,27.01) 86.17,23.9 86.17,21.85 arc(85.02,19.08) 82.25,17.93 R5.2
N16698666: length 12.2
  TOP w0.483: R2.1 TX_RX.1
N16698686: length 12.2
  TOP w0.483: ANT.1 R2.2
N1664008529: length 0.8
  TOP w0.25: 19,25.72 C8.2

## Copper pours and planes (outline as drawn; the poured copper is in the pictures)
GND on TOP (solid shape): 5.23,21.72 0.15,21.72 0.15,26.59 5.23,26.59
GND on TOP (solid shape): 5.23,15.41 0.15,15.41 0.15,20.27 5.23,20.27
GND on TOP (solid shape): 36.85,22.22 31.77,22.22 31.77,27.09 36.85,27.09
GND on TOP (solid shape): 36.85,15.91 31.77,15.91 31.77,20.77 36.85,20.77
GND on TOP, L2, L3: 36.75,0.25 0.25,0.25 0.25,45.75 36.75,45.75 ; 1 cut-out
GND on BOTTOM: 36.75,0.25 0.25,0.25 0.25,45.75 36.75,45.75
GND_FIELD SIGNAL on TOP (solid shape): 66.75,29.02 61.68,29.02 61.68,33.89 66.75,33.89
GND_FIELD SIGNAL on TOP (solid shape): 66.75,22.71 61.68,22.71 61.68,27.57 66.75,27.57
GND_FIELD SIGNAL on TOP (solid shape): 66.75,10.62 61.68,10.62 61.68,15.49 66.75,15.49
GND_FIELD SIGNAL on TOP (solid shape): 66.75,4.31 61.68,4.31 61.68,9.17 66.75,9.17
GND_FIELD SIGNAL on TOP (solid shape): 95.72,29.02 90.64,29.02 90.64,33.89 95.72,33.89
GND_FIELD SIGNAL on TOP (solid shape): 95.72,22.71 90.64,22.71 90.64,27.57 95.72,27.57
GND_FIELD SIGNAL on TOP (solid shape): 95.72,10.62 90.64,10.62 90.64,15.49 95.72,15.49
GND_FIELD SIGNAL on TOP (solid shape): 95.72,4.31 90.64,4.31 90.64,9.17 95.72,9.17
GND_FIELD SIGNAL on TOP: 95.65,35.95 95.65,2.25 61.75,2.25 61.75,35.95 ; 2 cut-outs
GND_FIELD SIGNAL on BOTTOM, L2, L3: 95.65,35.95 95.65,2.25 61.75,2.25 61.75,35.95
N16669932 on TOP (solid shape): 4.72,20.76 4.11,20.76 4.11,20.76 0.15,20.76 0.15,21.24 4.72,21.24
N16682817 on TOP (solid shape): 32.89,21.74 36.85,21.74 36.85,21.26 32.28,21.26 32.28,21.74 32.89,21.74
N16698570 on TOP (solid shape): 66.25,28.06 65.64,28.06 65.64,28.06 61.68,28.06 61.68,28.54 66.25,28.54
N16698590 on TOP (solid shape): 91.76,28.54 95.72,28.54 95.72,28.06 91.15,28.06 91.15,28.54 91.76,28.54
N16698666 on TOP (solid shape): 66.25,9.66 65.64,9.66 65.64,9.66 61.68,9.66 61.68,10.14 66.25,10.14
N16698686 on TOP (solid shape): 91.76,10.14 95.72,10.14 95.72,9.66 91.15,9.66 91.15,10.14 91.76,10.14

Small or netless copper shapes (teardrops, artwork), in the pictures only: 2 on TOP

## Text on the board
BOTTOM: TW23-D865-001_V1
Ref Des/Assembly Bottom: SECONDARY ASSEMBLY DRAWING SHOWN
Ref Des/Silkscreen Bottom: SILKSCREEN BOTTOM
User.Comments: CPW = 0.483 | CPW = N/A | W=N/A | TOL: +/-5%
Ref Des/Silkscreen Top: TxRx | VDET | GND | ANT | NC | VCC | CSD | CTX | CPS | SKY66122-11 EVB | PCB# TW23-D865-001_V1 | ASY# TW23-D860-001_V1 | SKY66122-11 | CALIBRATION BRD | SILKSCREEN TOP
User.20: PRIMARY ASSEMBLY DRAWING SHOWN
User.21: PRIMARY ASSEMBLY DRAWING SHOWN (V1)
User.27: 19 | N/A
User.45: SYMBOL | SIZE | 254.0 | 455.0 | 1000.0 | 1050.0 | PLATED | DRILL CHART: TOP to BOTTOM | ALL UNITS ARE IN MICRONS | QTY | 69 | 808 | 2 | 16 | TOLERANCE | +50.0/-50.0 | +75.0/-75.0 | SEE NOTE
